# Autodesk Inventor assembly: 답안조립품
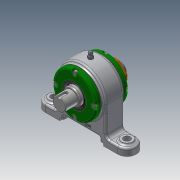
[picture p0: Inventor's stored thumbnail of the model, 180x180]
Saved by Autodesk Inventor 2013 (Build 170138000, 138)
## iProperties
Created: 2019-05
Part Number: 답안조립품
Document SubType Name: Assembly
Designer: a
Author: a
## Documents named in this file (13)
- C:\Users\a\Desktop\490504V1016\답안조립품.iam
- C:\Users\a\Desktop\490504V1016\본체.ipt
- C:\Users\a\Desktop\490504V1016\개스킷.ipt
- C:\Users\a\Desktop\490504V1016\그리스니플 M6.ipt
- 그리스니플  M6.ipt
- C:\Users\a\Desktop\490504V1016\그리스니플개스킷.ipt
- C:\Users\a\Desktop\490504V1016\베어링너트.ipt
- C:\Users\a\Desktop\490504V1016\볼트 M4.ipt
- C:\Users\a\Desktop\490504V1016\앵귤러 볼 베어링 7205.ipt
- C:\Users\a\Desktop\490504V1016\오일 실 28 40 5 B.ipt
- C:\Users\a\Desktop\490504V1016\축.ipt
- C:\Users\a\Desktop\490504V1016\칼라.ipt
- C:\Users\a\Desktop\490504V1016\커버.ipt
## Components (4 placed, 3 different names)
1. 개스킷:1
2. 그리스니플  M6:1
3. 그리스니플개스킷:1
4. 개스킷:2
